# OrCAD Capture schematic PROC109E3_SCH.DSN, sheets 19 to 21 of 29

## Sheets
19 19. BOOSTERPACK_CONNECTOR: size C; title: BOOSTERPACK CONNECTOR
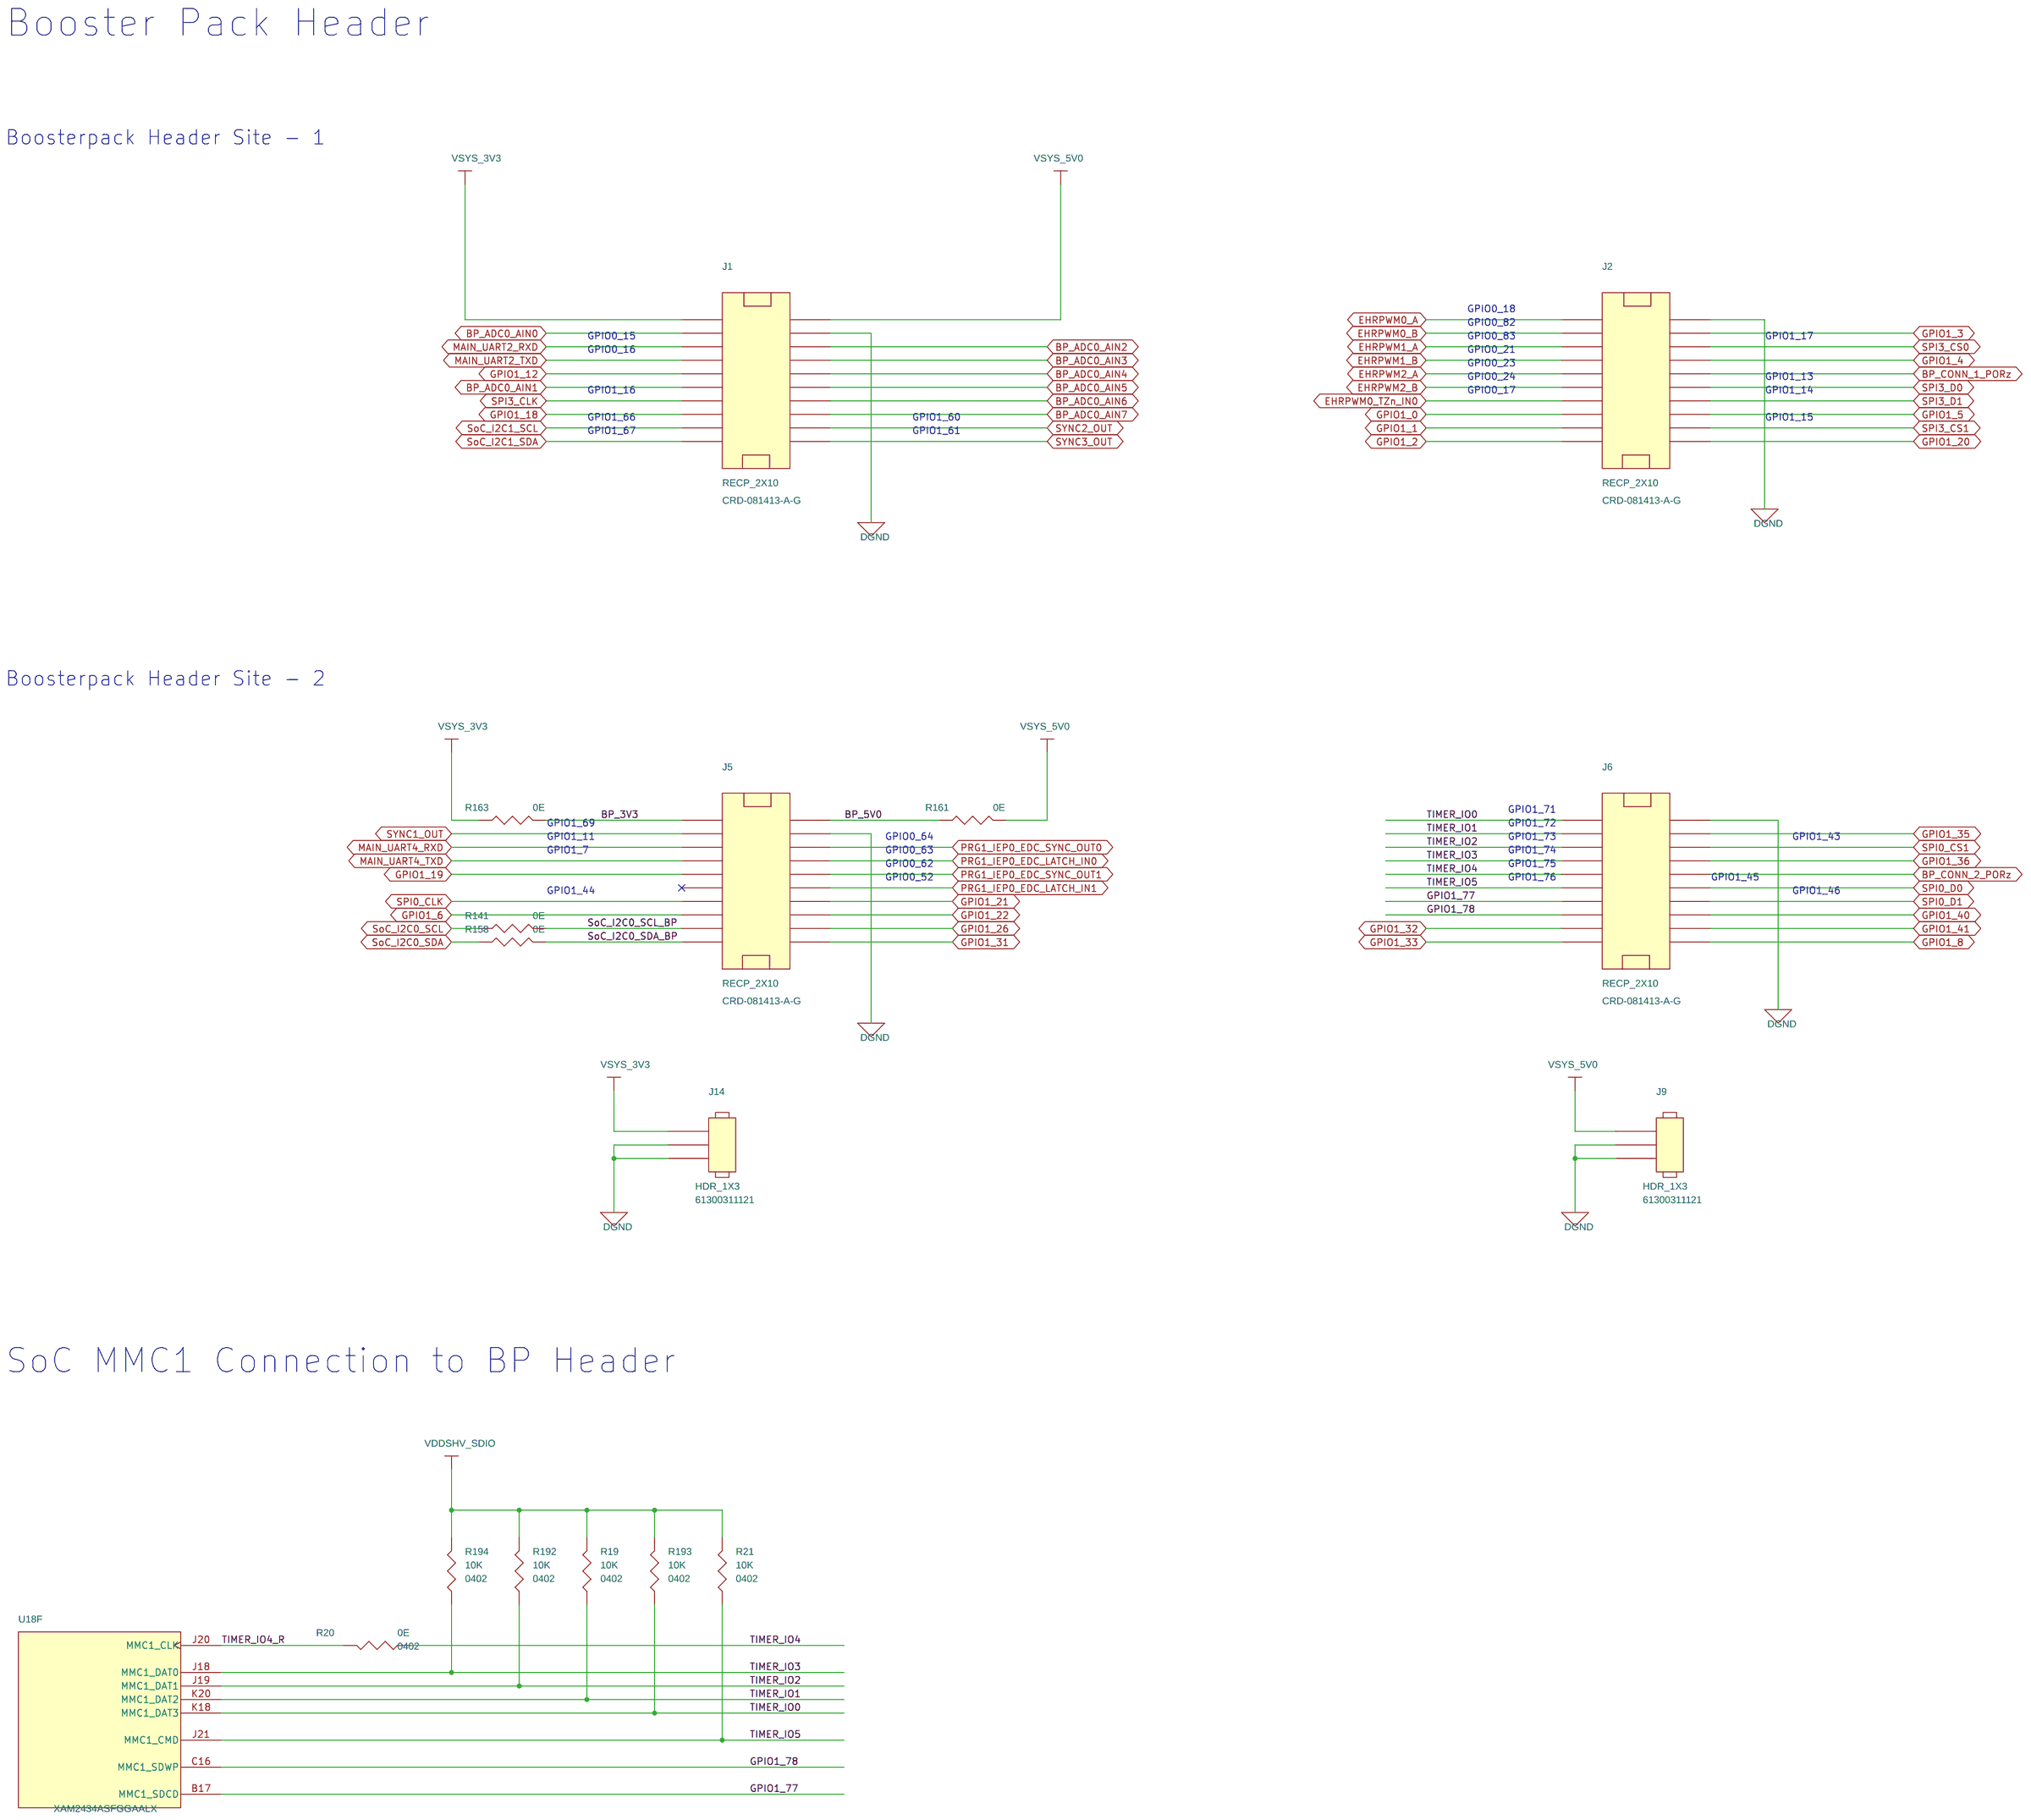
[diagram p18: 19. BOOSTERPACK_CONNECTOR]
20 20. TEST AUTOMATION HDR: size C; title: TEST AUTOMATION HEADER
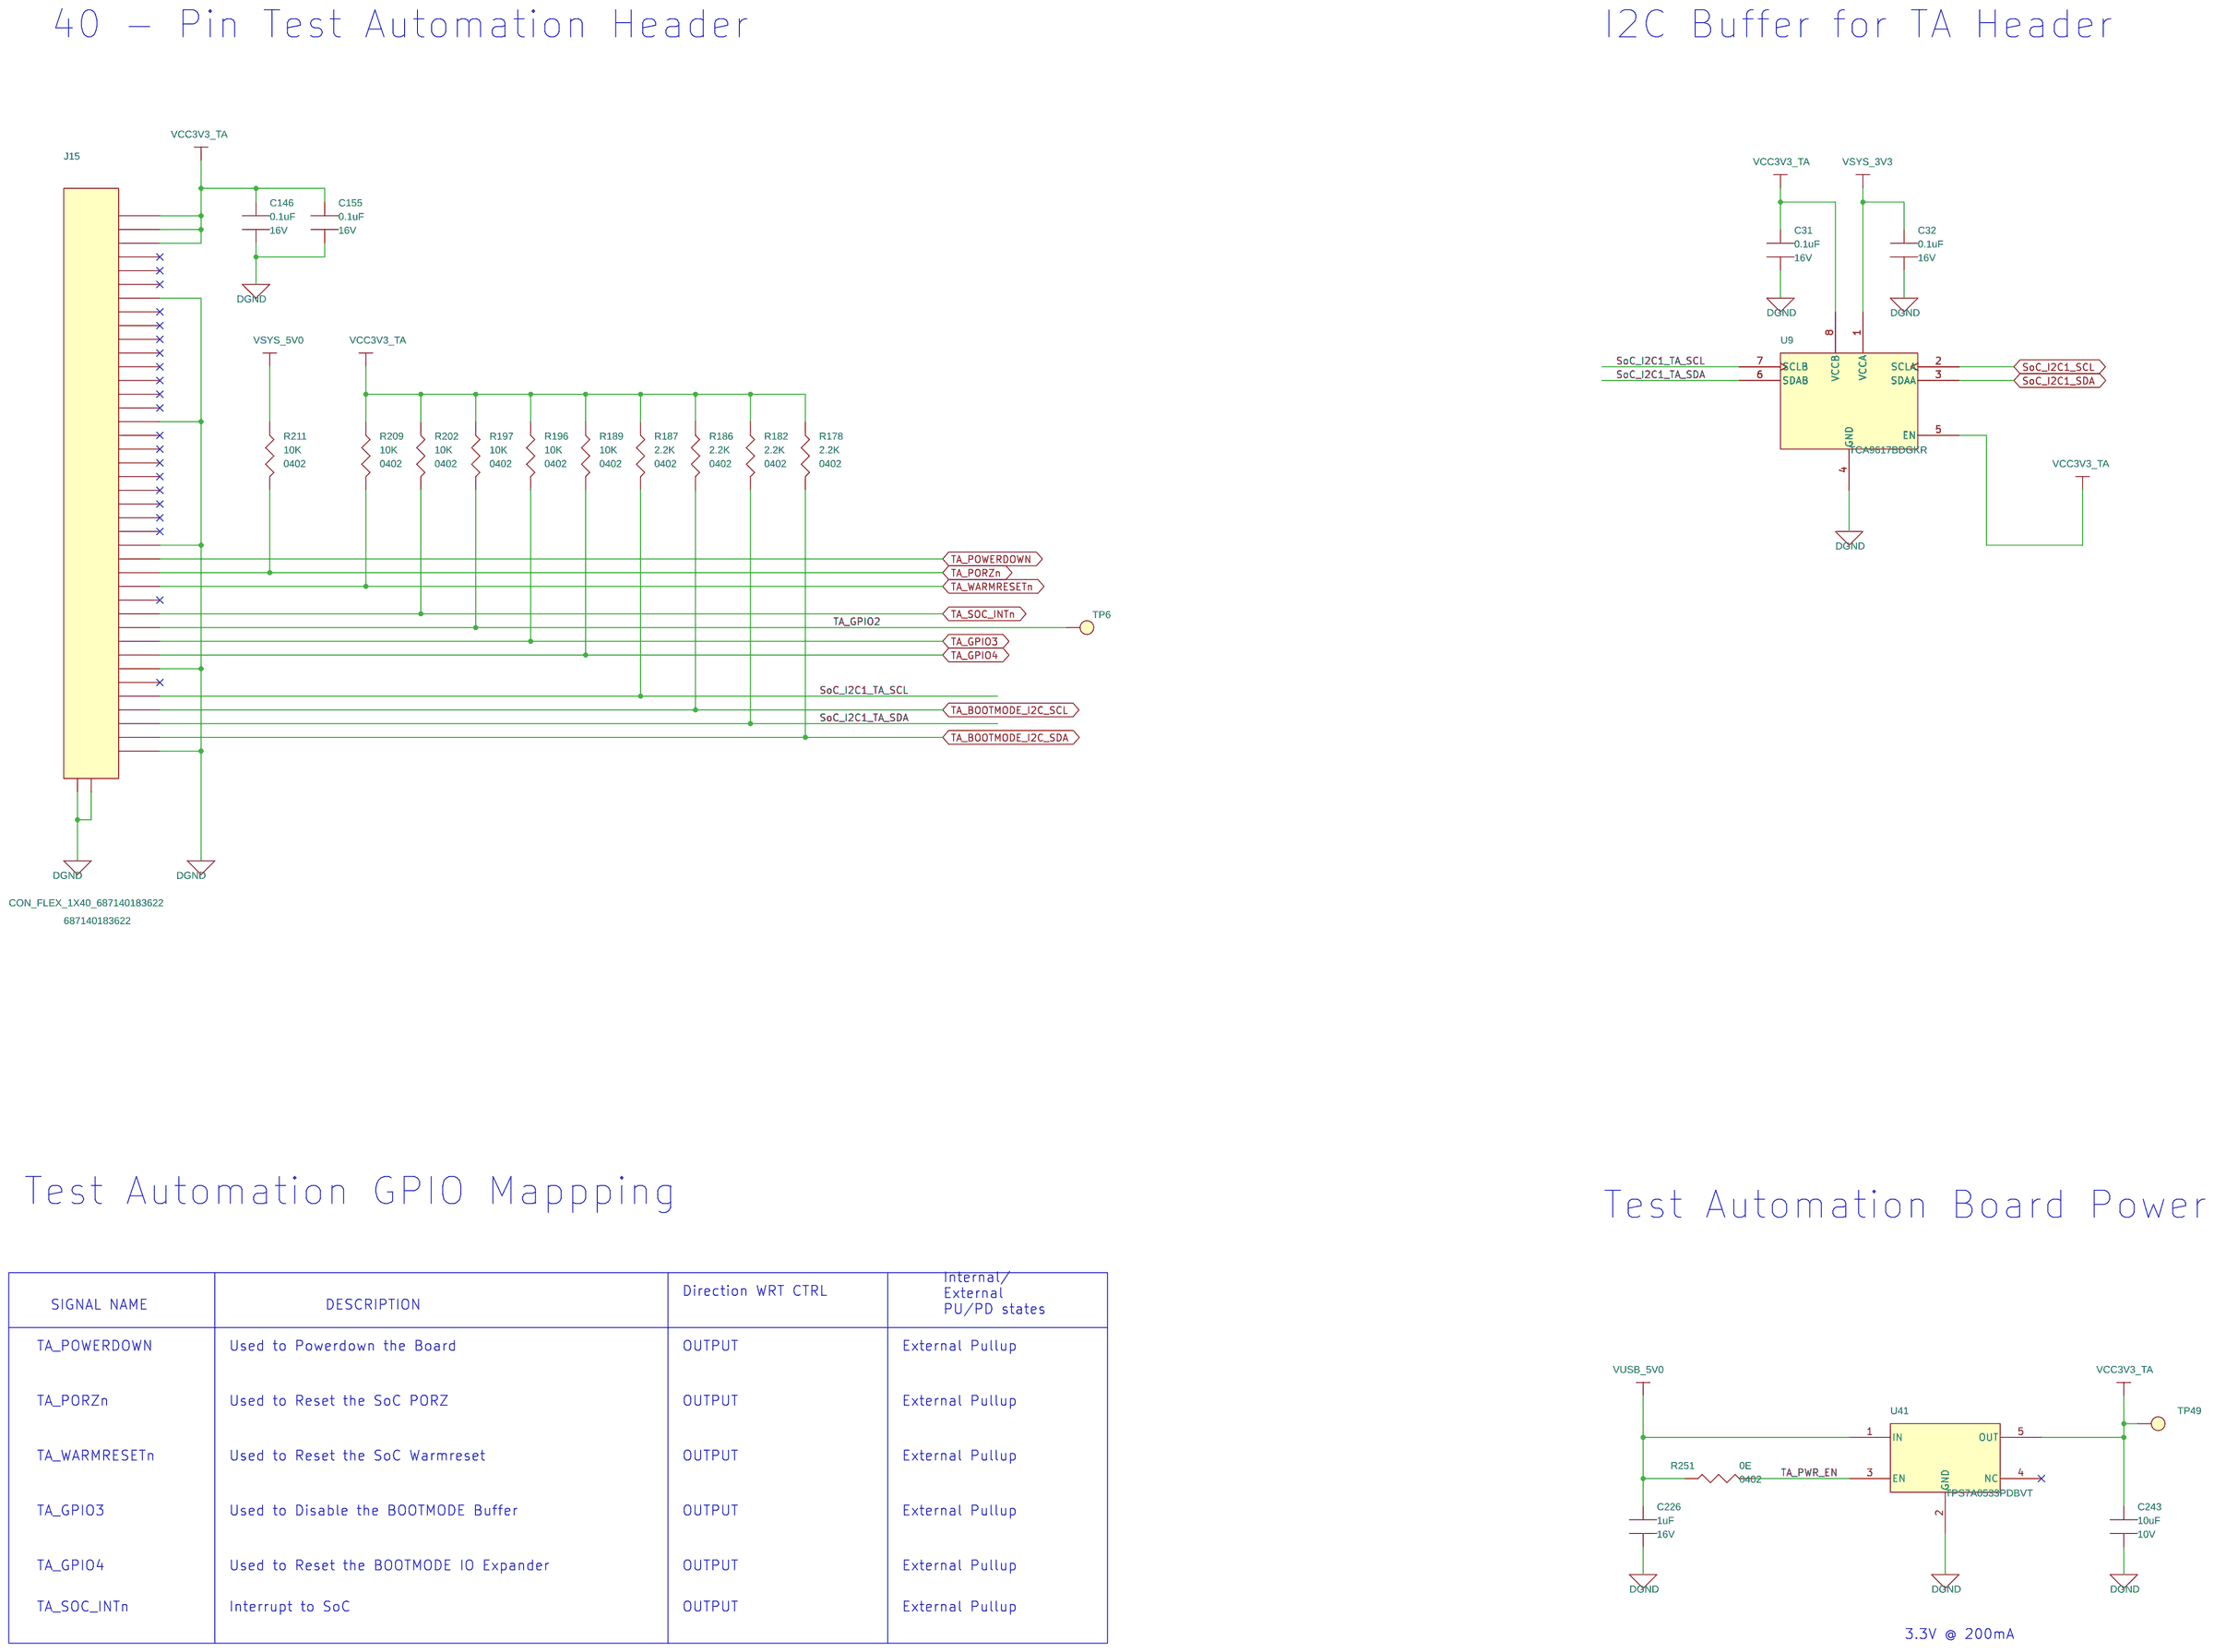
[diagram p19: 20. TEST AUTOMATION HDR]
21 21. BOOT MODE BUFFER & SWITCHES: size C; title: BOOT MODE BUFFER & SWITCHES
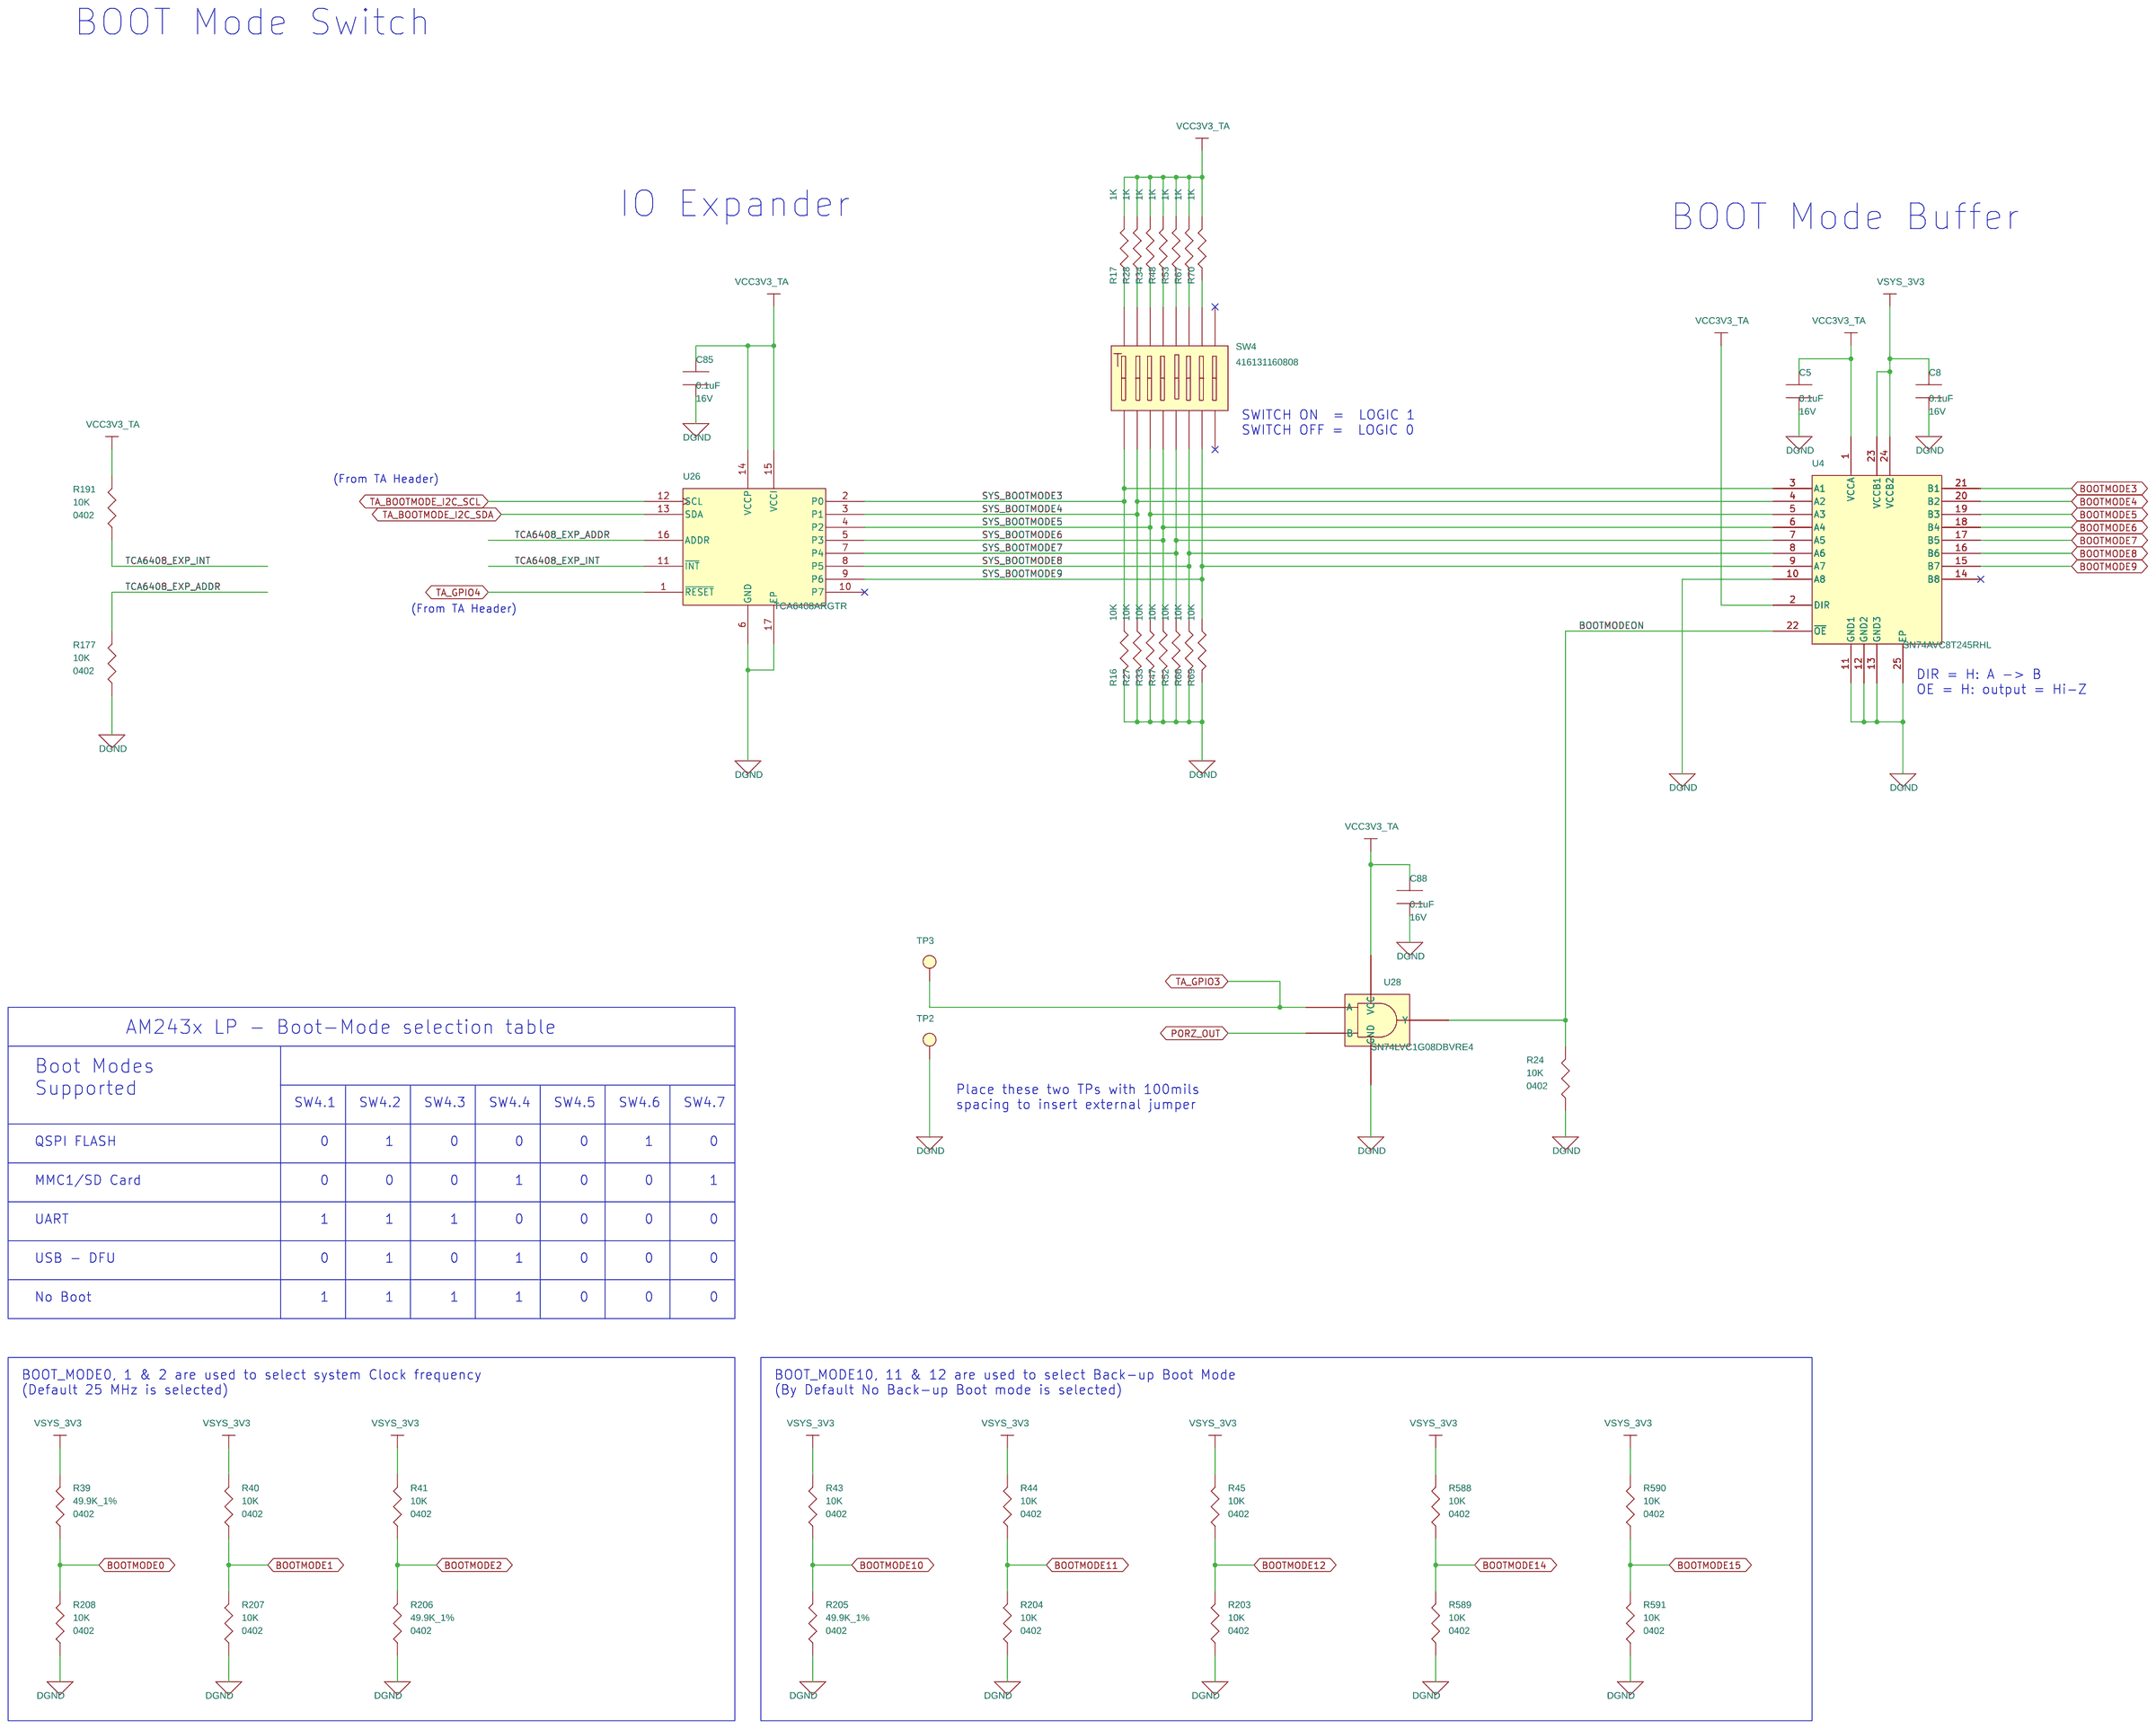
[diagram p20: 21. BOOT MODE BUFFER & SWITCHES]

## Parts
sheet 19. BOOSTERPACK_CONNECTOR
J1  RECP_2X10  [RECPT_2X10_CRD-081413-A_S_T_8-6]
J2  RECP_2X10  [RECPT_2X10_CRD-081413-A_S_T_8-6]
J5  RECP_2X10  [RECPT_2X10_CRD-081413-A_S_T_8-6]
J6  RECP_2X10  [RECPT_2X10_CRD-081413-A_S_T_8-6]
J9  HDR_1X3  [HDR_1X3_100_S_T]
J14  HDR_1X3  [HDR_1X3_100_S_T]
R19  10K  [RES0402_0-5]
R20  0E  [RES0402_0-5]
R21  10K  [RES0402_0-5]
R141  0E  [RES0402_0-5]
R158  0E  [RES0402_0-5]
R161  0E  [RES0402_0-5]
R163  0E  [RES0402_0-5]
R192  10K  [RES0402_0-5]
R193  10K  [RES0402_0-5]
R194  10K  [RES0402_0-5]
sheet 20. TEST AUTOMATION HDR
C31  0.1uF  [CAP0201_0-5]
C32  0.1uF  [CAP0201_0-5]
C146  0.1uF  [CAP0201_0-5]
C155  0.1uF  [CAP0201_0-5]
C226  1uF  [CAP0201_0-5]
C243  10uF  [CAP0402_0-75]
J15  CON_FLEX_1X40_687140183622  [CON_FLEX1X40_687140183622_S_R_S_1-3]
R178  2.2K  [RES0402_0-5]
R182  2.2K  [RES0402_0-5]
R186  2.2K  [RES0402_0-5]
R187  2.2K  [RES0402_0-5]
R189  10K  [RES0402_0-5]
R196  10K  [RES0402_0-5]
R197  10K  [RES0402_0-5]
R202  10K  [RES0402_0-5]
R209  10K  [RES0402_0-5]
R211  10K  [RES0402_0-5]
R251  0E  [RES0402_0-5]
TP6  TP20_SMD  [TP20_SMD]
TP49  TP20_SMD  [TP20_SMD]
U9  TCA9617BDGKR  [VSSOP8_25-59_120X120_1-1]
U41  TPS7A0533PDBVT  [SOT23-5_1-5]
sheet 21. BOOT MODE BUFFER & SWITCHES
C5  0.1uF  [CAP0201_0-5]
C8  0.1uF  [CAP0201_0-5]
C85  0.1uF  [CAP0201_0-5]
C88  0.1uF  [CAP0201_0-5]
R16  10K  [RES0402_0-5]
R17  1K  [RES0402_0-5]
R24  10K  [RES0402_0-5]
R27  10K  [RES0402_0-5]
R28  1K  [RES0402_0-5]
R33  10K  [RES0402_0-5]
R34  1K  [RES0402_0-5]
R39  49.9K_1%  [RES0402_0-5]
R40  10K  [RES0402_0-5]
R41  10K  [RES0402_0-5]
R43  10K  [RES0402_0-5]
R44  10K  [RES0402_0-5]
R45  10K  [RES0402_0-5]
R47  10K  [RES0402_0-5]
R48  1K  [RES0402_0-5]
R52  10K  [RES0402_0-5]
R53  1K  [RES0402_0-5]
R66  10K  [RES0402_0-5]
R67  1K  [RES0402_0-5]
R69  10K  [RES0402_0-5]
R70  1K  [RES0402_0-5]
R177  10K  [RES0402_0-5]
R191  10K  [RES0402_0-5]
R203  10K  [RES0402_0-5]
R204  10K  [RES0402_0-5]
R205  49.9K_1%  [RES0402_0-5]
R206  49.9K_1%  [RES0402_0-5]
R207  10K  [RES0402_0-5]
R208  10K  [RES0402_0-5]
R588  10K  [RES0402_0-5]
R589  10K  [RES0402_0-5]
R590  10K  [RES0402_0-5]
R591  10K  [RES0402_0-5]
SW4  416131160808  [SW16_416131160808_460X230_SMD_2-7]
TP2  THRU HOLE  [TP_40X65]
TP3  THRU HOLE  [TP_40X65]
U4  SN74AVC8T245RHL  [QFN24_19-68_220X140_1]
U26  TCA6408ARGTR  [QFN16_19-68_120X120_1_EP1-6]
U28  SN74LVC1G08DBVRE4  [SOT23-5]
sheet 25. SOC_ANALOG_POWER_DECAPs
U18  XAM2434ASFGGAALX  [BGA293_19-68_440X440_1]  (sections A,B,C,D,E,F,G,H,I,J,K,L,M)

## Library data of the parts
J1 J2 J5 J6 = RECP_10X2: CON RECP 2X10 2.54MM PITCH ST TH; Chkd/date: MANIRAJA/231120; Crtd /date: ALVY/201120; Custom_Duty: 24%; Customs_HS_Code: 85369090; Distributor_name: NA; Distributor_part_number: NA; Footprint Path: Y:\MIS_DATABASE\Library\ALTIUM_TOOL\PCB_FOOTPRINTS\Altium_Footprint_Lib.PcbLib; Height: 8.51MM; Library Path: Y:\MIS_DATABASE\Library\ALTIUM_TOOL\SCHEMATICS_PARTS\MS_CONNECTOR_Library.schlib; Mfr_name: MAJOR LEAGUE; Mfr_part_number: CRD-081413-A-G; Mistral Part No: 150020110025-R; Package: THRU-HOLE; Part_type: CONNECTOR\RECEPTACLE; Project: TI_AM243x LP EVM; RoHS: RoHS; Temperature: -40°C+105°C; Tolerance: NA; Voltage: NA; Wattage: NA; Weight: NA; Datasheet: Y:\MIS_DATABASE\DATASHEETS\CONNECTORS\CRD-081413-A.PDF
J9 J14 = HEADER_3X1: CON HDR 1X3 2.54MM PITCH ST TH; Chkd/date: VASANTHA/211015; Crtd /date: VASANTHA/211015; Custom_Duty: 24%; Customs_HS_Code: 85369090; Distributor_name: DIGIKEY; Distributor_part_number: 732-5316-ND; Height: 8.54MM; Mfr_name: WURTH ELECTRONICS INC; Mfr_part_number: 61300311121; Mistral Part No: 150015100037-R; Package: THRU-HOLE; Part_type: CONNECTOR\HEADERS; Project: CYPHY_ROADKILL; RoHS: RoHS; Temperature: NA; Tolerance: NA; Voltage: NA; Wattage: NA; Weight: NA; Datasheet: Y:\MIS_DATABASE\DATASHEETS\CONNECTORS\6130XXX.PDF
R16 R19 R21 R24 R27 R33 R40 R41 R43-R45 R47 R52 R66 R69 R177 R189 R191-R194 R196 R197 R202-R204 R207-R209 R211 R588-R591 = RESISTOR: RES 10K 1/16W 5% 0402; Chkd/date: VASANTHA/061216; Crtd /date: MAZHAR/230805; Custom_Duty: 15%; Customs_HS_Code: 85332119; Distributor_name: DIGIKEY; Distributor_part_number: 311-10KJRCT-ND; Footprint Path: Y:\MIS_DATABASE\Library\ALTIUM_TOOL\PCB_FOOTPRINTS\Altium_Footprint_Lib.PcbLib; Height: 0.40MM; Library Path: Y:\MIS_DATABASE\Library\ALTIUM_TOOL\SCHEMATICS_PARTS\MS_DISCRETE_Library.schlib; Mfr_name: YAGEO AMERICA; Mfr_part_number: RC0402JR-0710KL; Mistral Part No: 110011060021-R; Package: 0402; Part_type: RESISTORS\FIXED; Project: HSE; RoHS: RoHS; Temperature: -55°C+155°C; Tolerance: 5%; Voltage: NA; Wattage: 1/16W; Weight: 0.65mg; Datasheet: Y:\MIS_DATABASE\DATASHEETS\RESISTORS\RCXXXXL-SER_MAR18.PDF
R20 = RESISTOR: RES 0E 1/16W 5% 0402; Chkd/date: VASANTHA/291216; Crtd /date: CHAITHANYA/300911; Custom_Duty: 15%; Customs_HS_Code: 85332119; Distributor_name: DIGIKEY; Distributor_part_number: 311-0.0JRCT-ND; Footprint Path: Y:\MIS_DATABASE\Library\ALTIUM_TOOL\PCB_FOOTPRINTS\Altium_Footprint_Lib.PcbLib; Height: 0.40MM; Library Path: Y:\MIS_DATABASE\Library\ALTIUM_TOOL\SCHEMATICS_PARTS\MS_DISCRETE_Library.schlib; Mfr_name: YAGEO AMERICA; Mfr_part_number: RC0402JR-070RL; Mistral Part No: 110011090036-R; Package: 0402; Part_type: RESISTORS\FIXED; Project: VP-4000-PROCESSOR; RoHS: RoHS; SIGNAL_MODEL: RESISTOR_RES0402_0-5_0E_0E; Temperature: -55°C+155°C; Tolerance: 5%; Voltage: NA; Wattage: 1/16W; Weight: 0.65mg; Datasheet: Y:\MIS_DATABASE\DATASHEETS\RESISTORS\RCXXXXL-SER_MAR18.PDF
R141 R158 R161 R163 R251 = RESISTOR: RES 0E 1/16W 5% 0402; Chkd/date: VASANTHA/291216; Crtd /date: CHAITHANYA/300911; Custom_Duty: 15%; Customs_HS_Code: 85332119; Distributor_name: DIGIKEY; Distributor_part_number: 311-0.0JRCT-ND; Footprint Path: Y:\MIS_DATABASE\Library\ALTIUM_TOOL\PCB_FOOTPRINTS\Altium_Footprint_Lib.PcbLib; Height: 0.40MM; Library Path: Y:\MIS_DATABASE\Library\ALTIUM_TOOL\SCHEMATICS_PARTS\MS_DISCRETE_Library.schlib; Mfr_name: YAGEO AMERICA; Mfr_part_number: RC0402JR-070RL; Mistral Part No: 110011090036-R; Package: 0402; Part_type: RESISTORS\FIXED; Project: VP-4000-PROCESSOR; RoHS: RoHS; Temperature: -55°C+155°C; Tolerance: 5%; Voltage: NA; Wattage: 1/16W; Weight: 0.65mg; Datasheet: Y:\MIS_DATABASE\DATASHEETS\RESISTORS\RCXXXXL-SER_MAR18.PDF
C5 C8 C31 C32 C85 C88 C146 C155 = CAP: CAP CERAMIC 0.1uF 16V 10% X5R 0201; Alt_Mfr_name: YAGEO AMERICA; Alt_Mfr_part_number: CC0402KRX5R8BB104; Chkd/date: MANIRAJA/230118; Crtd /date: MANIRAJA/230118; Custom_Duty: 15%; Customs_HS_Code: 85322990; Distributor_name: DIGIKEY; Distributor_part_number: 490-14305-1-ND; Footprint Path: Y:\MIS_DATABASE\Library\ALTIUM_TOOL\PCB_FOOTPRINTS\Altium_Footprint_Lib.PcbLib; Height: 0.33MM; Library Path: Y:\MIS_DATABASE\Library\ALTIUM_TOOL\SCHEMATICS_PARTS\MS_DISCRETE_Library.schlib; Mfr_name: MURATA; Mfr_part_number: GRM033R61C104KE14D; Mistral Part No: 120009030072-R; Package: 0201; Part_type: CAPACITORS\CERAMIC; Project: TI_MAXIE_CPB; RoHS: RoHS; Temperature: -55°C+85°C; Tolerance: 10%; Voltage: 16V; Wattage: NA; Weight: 0.33mg; Datasheet: Y:\MIS_DATABASE\DATASHEETS\CAPACITORS\GRM033R61C104KE14.PDF
C226 = CAP: CAP CERAMIC 1uF 16V 20% X5R 0201; Chkd/date: MANIRAJA/300520; Crtd /date: ALVY/260520; Custom_Duty: 15%; Customs_HS_Code: 85322990; Distributor_name: DIGIKEY; Distributor_part_number: 490-18654-1-ND; Footprint Path: Y:\MIS_DATABASE\Library\ALTIUM_TOOL\PCB_FOOTPRINTS\Altium_Footprint_Lib.PcbLib; Height: 0.39MM; Library Path: Y:\MIS_DATABASE\Library\ALTIUM_TOOL\SCHEMATICS_PARTS\MS_DISCRETE_Library.schlib; Mfr_name: MURATA; Mfr_part_number: GRM033R61C105ME15D; Mistral Part No: 120018090038-R; Package: 0201; Part_type: CAPACITORS\CERAMIC; Project: QCS610_NANOSOM; RoHS: RoHS; Temperature: -55°C+85°C; Tolerance: 20%; Voltage: 16V; Wattage: NA; Weight: 0.33mg; Datasheet: Y:\MIS_DATABASE\DATASHEETS\CAPACITORS\GRM033R61C105ME15.PDF
C243 = CAP: CAP CERAMIC 10uF 10V 20% X5R 0402; Chkd/date: MANIRAJA/300520; Crtd /date: ALVY/260520; Custom_Duty: 15%; Customs_HS_Code: 85322990; Distributor_name: DIGIKEY; Distributor_part_number: 490-GRM155R61A106ME11DTR-ND; Footprint Path: Y:\MIS_DATABASE\Library\ALTIUM_TOOL\PCB_FOOTPRINTS\Altium_Footprint_Lib.PcbLib; Height: 0.55MM; Library Path: Y:\MIS_DATABASE\Library\ALTIUM_TOOL\SCHEMATICS_PARTS\MS_DISCRETE_Library.schlib; Mfr_name: MURATA; Mfr_part_number: GRM155R61A106ME11D; Mistral Part No: 120013110019-R; Package: 0402; Part_type: CAPACITORS\CERAMIC; Project: QCS610_NANOSOM; RoHS: RoHS; Temperature: -55°C+85°C; Tolerance: 20%; Voltage: 10V; Wattage: NA; Weight: 3.1mg; Datasheet: Y:\MIS_DATABASE\DATASHEETS\CAPACITORS\MURATA-GXX-SER_NOV17.PDF
J15 = CON_FLEX_40X1_20347: CON FPC 1X40 0.50MM PITCH FEMALE RT SMD; Chkd/date: ALVY/101220; Crtd /date: MANIRAJA/101220; Custom_Duty: 24%; Customs_HS_Code: 85369090; Distributor_name: NA; Distributor_part_number: NA; Footprint Path: Y:\MIS_DATABASE\Library\ALTIUM_TOOL\PCB_FOOTPRINTS\Altium_Footprint_Lib.PcbLib; Height: 1.30MM; Library Path: Y:\MIS_DATABASE\Library\ALTIUM_TOOL\SCHEMATICS_PARTS\MS_CONNECTOR_Library.schlib; Mfr_name: WURTH ELEKTRONIK; Mfr_part_number: 687140183622; Mistral Part No: 150020120010-R; Package: SMD; Part_type: CONNECTOR\FPC; Project: TI_AM243x LP EVM; RoHS: RoHS; Temperature: -25°C+85°C; Tolerance: NA; Voltage: NA; Wattage: NA; Weight: NA; Datasheet: Y:\MIS_DATABASE\DATASHEETS\CONNECTORS\687140183622.PDF
R178 R182 R186 R187 = RESISTOR: RES 2.2K 1/16W 5% 0402; Chkd/date: VASANTHA/061216; Crtd /date: BAVISH/021210; Custom_Duty: 15%; Customs_HS_Code: 85332119; Distributor_name: DIGIKEY; Distributor_part_number: 311-2.2KJRCT-ND; Footprint Path: Y:\MIS_DATABASE\Library\ALTIUM_TOOL\PCB_FOOTPRINTS\Altium_Footprint_Lib.PcbLib; Height: 0.40MM; Library Path: Y:\MIS_DATABASE\Library\ALTIUM_TOOL\SCHEMATICS_PARTS\MS_DISCRETE_Library.schlib; Mfr_name: YAGEO AMERICA; Mfr_part_number: RC0402JR-072K2L; Mistral Part No: 110010120018-R; Package: 0402; Part_type: RESISTORS\FIXED; Project: TE4; RoHS: RoHS; Temperature: -55°C+155°C; Tolerance: 5%; Voltage: NA; Wattage: 1/16W; Weight: 0.65mg; Datasheet: Y:\MIS_DATABASE\DATASHEETS\RESISTORS\RCXXXXL-SER_MAR18.PDF
TP6 TP49 = TESTPOINT: TESTPOINT CIR 20 SMD; Chkd/date: SHREESHAIL/171006; Crtd /date: MAZHAR/171006; Custom_Duty: NA; Customs_HS_Code: NA; Distributor_name: NA; Distributor_part_number: NA; Footprint Path: Y:\MIS_DATABASE\Library\ALTIUM_TOOL\PCB_FOOTPRINTS\Altium_Footprint_Lib.PcbLib; Height: NA; Library Path: Y:\MIS_DATABASE\Library\ALTIUM_TOOL\SCHEMATICS_PARTS\MS_DISCRETE_Library.schlib; MECHANICAL 3D STEP FILE: NA; Mfr_name: LOCAL; Mistral Part No: NA; Package: SMD; Project: BT MODULE_CSRBC04; RoHS: NA; Temperature: NA; Tolerance: NA; Voltage: NA; Wattage: NA; Weight: NA; Datasheet: NA
U9 = TCA9617BDGKR_VSSOP8: IC FM+I2C BUS REPEATER LEVEL TRANSLATOR VSSOP8; Chkd/date: MANIRAJA/131017; Crtd /date: MANIRAJA/131017; Custom_Duty: 15%; Customs_HS_Code: 85423100; Distributor_name: DIGIKEY; Distributor_part_number: 296-40579-1-ND; Height: 1.10MM; Mfr_name: TEXAS INSTRUMENTS; Mistral Part No: 141017100010-R; Package: VSSOP8; Part_type: ICS\INTERFACE\LEVEL TRANSLATOR; Project: TI_MAXIE_CPB; RoHS: RoHS; Temperature: -40°C+85°C; Tolerance: NA; Voltage: NA; Wattage: NA; Weight: NA; Datasheet: Y:\MIS_DATABASE\DATASHEETS\ICS\INTERFACE\TCA9617B.PDF
U41 = TLV71318PDBVT_SOT23-5: IC 1uA ULTRA-LOW IQ 200mA LDO REGULATOR SOT23-5; Chkd/date: MANIRAJA/131120; Crtd /date: ALVY/121120; Custom_Duty: 15%; Customs_HS_Code: 85423100; Distributor_name: DIGIKEY; Distributor_part_number: 296-50256-1-ND; Footprint Path: Y:\MIS_DATABASE\Library\ALTIUM_TOOL\PCB_FOOTPRINTS\Altium_Footprint_Lib.PcbLib; Height: 1.45MM; Library Path: Y:\MIS_DATABASE\Library\ALTIUM_TOOL\SCHEMATICS_PARTS\MS_MISCPOWER_Library.schlib; Mfr_name: TEXAS INSTRUMENTS; Mistral Part No: 142020110015-R; Package: SOT23-5; Part_type: ICS\POWER\VOLTAGE REGULATOR; Project: TI_AM243x LP EVM; RoHS: RoHS; Temperature: -40°C+125°C; Tolerance: NA; Voltage: NA; Wattage: NA; Weight: 25.3mg; Datasheet: Y:\MIS_DATABASE\DATASHEETS\MISC\REGULATORS\TPS7A05XX.PDF
R17 R28 R34 R48 R53 R67 R70 = RESISTOR: RES 1K 1/16W 5% 0402; Chkd/date: VASANTHA/120516; Crtd /date: VASANTHA/120516; Custom_Duty: 15%; Customs_HS_Code: 85332119; Distributor_name: DIGIKEY; Distributor_part_number: 311-1.0KJRCT-ND; Footprint Path: Y:\MIS_DATABASE\Library\ALTIUM_TOOL\PCB_FOOTPRINTS\Altium_Footprint_Lib.PcbLib; Height: 0.40MM; Library Path: Y:\MIS_DATABASE\Library\ALTIUM_TOOL\SCHEMATICS_PARTS\MS_DISCRETE_Library.schlib; Mfr_name: YAGEO AMERICA; Mfr_part_number: RC0402JR-071KL; Mistral Part No: 110010070006-R; Package: 0402; Part_type: RESISTORS\FIXED; Project: TMDXCSK368; RoHS: RoHS; Temperature: -55°C+155°C; Tolerance: 5%; Voltage: NA; Wattage: 1/16W; Weight: 0.65mg; Datasheet: Y:\MIS_DATABASE\DATASHEETS\RESISTORS\RCXXXXL-SER_MAR18.PDF
R39 R205 R206 = RESISTOR: RES 49.9K 1/10W 1% 0402; Chkd/date: MANIRAJA/130617; Crtd /date: BAVISH/020611; Custom_Duty: 15%; Customs_HS_Code: 85332119; Distributor_name: DIGIKEY; Distributor_part_number: P49.9KLCT-ND; Footprint Path: Y:\MIS_DATABASE\Library\ALTIUM_TOOL\PCB_FOOTPRINTS\Altium_Footprint_Lib.PcbLib; Height: 0.40MM; Library Path: Y:\MIS_DATABASE\Library\ALTIUM_TOOL\SCHEMATICS_PARTS\MS_DISCRETE_Library.schlib; Mfr_name: PANASONIC-ECG; Mfr_part_number: ERJ-2RKF4992X; Mistral Part No: 110011060018-R; Package: 0402; Part_type: RESISTORS\FIXED; Project: AM4515_EVM_LCD; RoHS: RoHS; Temperature: -55°C+155°C; Tolerance: 1%; Voltage: NA; Wattage: 1/10W; Weight: 0.8mg; Datasheet: Y:\MIS_DATABASE\DATASHEETS\RESISTORS\PAN-ERJSER_NOV17.PDF
SW4 = SW16_CHS-08A: SWITCH SLIDE SPST ST SMD; Chkd/date: MANIRAJA/051020; Crtd /date: ALVY/011020; Custom_Duty: 24%; Customs_HS_Code: 85369090; Distributor_name: DIGIKEY; Distributor_part_number: 732-3857-1-ND; Footprint Path: Y:\MIS_DATABASE\Library\ALTIUM_TOOL\PCB_FOOTPRINTS\Altium_Footprint_Lib.PcbLib; Height: 2.65MM; Library Path: Y:\MIS_DATABASE\Library\ALTIUM_TOOL\SCHEMATICS_PARTS\MS_SWITCH_Library.schlib; Mfr_name: WURTH ELECTRONICS; Mistral Part No: 130020100001-R; Package: SMD; Part_type: ELECTRO-MECHANICAL\SWITCH; Project: AM64X_SKEVM; RoHS: RoHS; Temperature: -40°C+85°C; Tolerance: NA; Voltage: NA; Wattage: NA; Weight: 281.7mg; Datasheet: Y:\MIS_DATABASE\DATASHEETS\MISC\SWITCHES\4161311608XX.PDF
TP2 TP3 = TESTPOINT: TESTPOINT 1.0MM DRILL PTH; Chkd/date: MAZHAR/271211; Crtd /date: SHREESHAIL/041005; Distributor_name: NA; Distributor_part_number: NA; Height: NA; Mfr_name: LOCAL; Mistral Part No: 130009030938; Package: THRU-HOLE; Project: HSE; Datasheet: NA
U4 = SN74AVC8T245RHL_QFN24: IC BUS TRANSCEIVER 8-BIT DUAL-SUPPLY QFN24; Chkd/date: VASANTHA/231216; Crtd /date: BAVISH/290411; Custom_Duty: 15%; Customs_HS_Code: 85423100; Distributor_name: DIGIKEY; Distributor_part_number: 296-17859-1-ND; Height: 1.00MM; Mfr_name: TEXAS INSTRUMENTS; Mfr_part_number: SN74AVC8T245RHLR; Mistral Part No: 143011040001-R; Package: QFN24; Part_type: ICS\TELECOM\TRANSCEIVER; Project: OMAPL1_PEC20; RoHS: RoHS; Temperature: -40°C+85°C; Tolerance: NA; Voltage: NA; Wattage: NA; Weight: NA; Datasheet: Y:\MIS_DATABASE\DATASHEETS\ICS\DIGITAL\BUSTRANSCEIVER\SN74AVC8T245.PDF
U26 = TCA6408ARGTR_VQFN16: IC 8-BIT I2C AND SMBUS I/O EXPANDER WITH INTERRUPT O/P VQFN16; Chkd/date: MANIRAJA/151018; Crtd /date: MANIRAJA/151018; Custom_Duty: 15%; Customs_HS_Code: 85423100; Distributor_name: DIGIKEY; Distributor_part_number: 296-24825-1-ND; Footprint Path: Y:\MIS_DATABASE\Library\ALTIUM_TOOL\PCB_FOOTPRINTS\Altium_Footprint_Lib.PcbLib; Height: 1.00MM; Library Path: Y:\MIS_DATABASE\Library\ALTIUM_TOOL\SCHEMATICS_PARTS\MS_MISCINTERFACE_Library.schlib; Mfr_name: TEXAS INSTRUMENTS; Mistral Part No: 141018100011-R; Package: VQFN16; Part_type: ICS\INTERFACE; Project: TI_60GHz-AOP; RoHS: RoHS; Temperature: -40°C+85°C; Tolerance: NA; Voltage: NA; Wattage: NA; Weight: 24.1mg; Datasheet: Y:\MIS_DATABASE\DATASHEETS\ICS\INTERFACE\TCA6408AXX.PDF
U28 = SN74LVC1G08DBVRE4_SOT23-5: IC SINGLE 2-INPUT POSITIVE AND GATE SOT23-5; Automotive Alternate_mfr_name: TEXAS INSTRUMENTS; Automotive Alternate_mfr_part_number: SN74LVC1G08QDBVRQ1; Chkd/date: SUHAS/221010; Crtd /date: USMAN/151008; Custom_Duty: 15%; Customs_HS_Code: 85423100; Distributor_name: DIGIKEY; Distributor_part_number: SN74LVC1G08DBVRE4-ND; Height: 1.45MM; Mfr_name: TEXAS INSTRUMENTS; Mistral Part No: 141009060026-R; Part_type: ICS\DIGITAL\GATES; Project: KHAN_MAIN; RoHS: Sb/ Br FREE; Temperature: -40°C+85°C; Datasheet: Y:\MIS_DATABASE\DATASHEETS\ICS\DIGITAL\GATES\SN74LVC1G08.PDF
U18 = AM243X_SOC_LP_EVM_BGA293: IC AM243x SoC_LP_EVM MICROPROCESSOR BGA293; Chkd/date: MANIRAJA/131120; Crtd /date: ALVY/121120; Custom_Duty: 15%; Customs_HS_Code: 85423100; Distributor_name: NA; Distributor_part_number: NA; Footprint Path: Y:\MIS_DATABASE\Library\ALTIUM_TOOL\PCB_FOOTPRINTS\Altium_Footprint_Lib.PcbLib; Height: 1.00MM; Library Path: Y:\MIS_DATABASE\Library\ALTIUM_TOOL\SCHEMATICS_PARTS\MS_MICROPROCESSOR_Library.schlib; Library Ref: AM243x SoC_LP_EVM_BGA293; Mfr_name: TEXAS INSTRUMENTS; Mistral Part No: 141220110003; Package: BGA293; Part_type: ICS\DIGITAL\MICROPROCESSOR; Project: TI_AM243x LP EVM; RoHS: NA; Temperature: NA; Tolerance: NA; Voltage: NA; Wattage: NA; Weight: NA; Datasheet: Y:\MIS_DATABASE\DATASHEETS\ICS\DIGITAL\MICROCONTROLLER\AM243x SoC-FP.PDF

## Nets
DGND: C5.2 C8.2 C31.2 C32.2 C85.2 C88.2 C146.2 C155.2 C226.2 C243.2 J1.4 J2.2 J5.4 J6.2 J9.2 J9.3 J14.2 J14.3 J15.7 J15.16 J15.25 J15.34 J15.40 J15.41 J15.42 R16.2 R24.1 R27.2 R33.2 R47.2 R52.2 R66.2 R69.2 R177.1 R203.1 R204.1 R205.1 R206.1 R207.1 R208.1 R589.1 R591.1 TP2.1(TP) U4.10(A8) U4.11(GND1) U4.12(GND2) U4.13(GND3) U4.25(EP) U9.4(GND) U26.6(GND) U26.17(EP) U28.3(GND) U41.2(GND) ; also on sheet 10 11 12 13 14 15 16 17 18 22 23 24 25 26 27 28
VCC3V3_TA: C5.1 C31.1 C85.1 C88.1 C146.1 C155.1 C243.1 J15.1 J15.2 J15.3 R17.2 R28.2 R34.2 R48.2 R53.2 R67.2 R70.2 R178.1 R182.1 R186.1 R187.1 R189.2 R191.2 R196.2 R197.2 R202.2 R209.2 TP49.1(TP) U4.1(VCCA) U4.2(DIR) U9.5(EN) U9.8(VCCB) U26.14(VCCP) U26.15(VCCI) U28.5(VCC) U41.5(OUT)
VDDSHV_SDIO: R19.2 R21.2 R192.2 R193.2 R194.2 ; also on sheet 24
BOOTMODE0: R39.1 R208.2 ; also on sheet 11
BOOTMODE1: R40.1 R207.2 ; also on sheet 11
BOOTMODE2: R41.1 R206.2 ; also on sheet 11
BOOTMODE3: U4.21(B1) ; also on sheet 11
BOOTMODE4: U4.20(B2) ; also on sheet 11
BOOTMODE5: U4.19(B3) ; also on sheet 11
BOOTMODE6: U4.18(B4) ; also on sheet 11
BOOTMODE7: U4.17(B5) ; also on sheet 11
BOOTMODE8: U4.16(B6) ; also on sheet 11
BOOTMODE9: U4.15(B7) ; also on sheet 11
BOOTMODE10: R43.1 R205.2 ; also on sheet 11
BOOTMODE11: R44.1 R204.2 ; also on sheet 11
BOOTMODE12: R45.1 R203.2 ; also on sheet 11
BOOTMODE14: R588.1 R589.2 ; also on sheet 11
BOOTMODE15: R590.1 R591.2 ; also on sheet 11
BOOTMODEON: R24.2 U4.22(~{OE}) U28.4(Y)
BP_3V3: J5.1 R163.2
BP_5V0: J5.2 R161.1
BP_ADC0_AIN0: J1.3 ; also on sheet 16
BP_ADC0_AIN1: J1.11 ; also on sheet 16
BP_ADC0_AIN2: J1.6 ; also on sheet 16
BP_ADC0_AIN3: J1.8 ; also on sheet 16
BP_ADC0_AIN4: J1.10 ; also on sheet 16
BP_ADC0_AIN5: J1.12 ; also on sheet 16
BP_ADC0_AIN6: J1.14 ; also on sheet 16
BP_ADC0_AIN7: J1.16 ; also on sheet 16
BP_CONN_1_PORz: J2.10 ; also on sheet 10
BP_CONN_2_PORz: J6.10 ; also on sheet 10
EHRPWM0_A: J2.1 ; also on sheet 11
EHRPWM0_B: J2.3 ; also on sheet 11
EHRPWM0_TZn_IN0: J2.13 ; also on sheet 11
EHRPWM1_A: J2.5 ; also on sheet 11
EHRPWM1_B: J2.7 ; also on sheet 11
EHRPWM2_A: J2.9 ; also on sheet 13
EHRPWM2_B: J2.11 ; also on sheet 13
GPIO1_0: J2.15 ; also on sheet 11
GPIO1_1: J2.17 ; also on sheet 11
GPIO1_2: J2.19 ; also on sheet 11
GPIO1_3: J2.4 ; also on sheet 11
GPIO1_4: J2.8 ; also on sheet 11
GPIO1_5: J2.16 ; also on sheet 11
GPIO1_6: J5.15 ; also on sheet 11
GPIO1_8: J6.20 ; also on sheet 11
GPIO1_12: J1.9 ; also on sheet 11
GPIO1_18: J1.15 ; also on sheet 11
GPIO1_19: J5.9 ; also on sheet 11
GPIO1_20: J2.20 ; also on sheet 11
GPIO1_21: J5.14 ; also on sheet 11
GPIO1_22: J5.16 ; also on sheet 11
GPIO1_26: J5.18 ; also on sheet 11
GPIO1_31: J5.20 ; also on sheet 11
GPIO1_32: J6.17 ; also on sheet 11
GPIO1_33: J6.19 ; also on sheet 11
GPIO1_35: J6.4 ; also on sheet 11
GPIO1_36: J6.8 ; also on sheet 11
GPIO1_40: J6.16 ; also on sheet 11
GPIO1_41: J6.18 ; also on sheet 11
GPIO1_77: J6.13 U18.B17(MMC1_SDCD)
GPIO1_78: J6.15 U18.C16(MMC1_SDWP)
MAIN_UART2_RXD: J1.5 ; also on sheet 11
MAIN_UART2_TXD: J1.7 ; also on sheet 11
MAIN_UART4_RXD: J5.5 ; also on sheet 11
MAIN_UART4_TXD: J5.7 ; also on sheet 11
PORZ_OUT: U28.2(B) ; also on sheet 11 12 15 17 18
PRG1_IEP0_EDC_LATCH_IN0: J5.8 ; also on sheet 12
PRG1_IEP0_EDC_LATCH_IN1: J5.12 ; also on sheet 12
PRG1_IEP0_EDC_SYNC_OUT0: J5.6 ; also on sheet 12
PRG1_IEP0_EDC_SYNC_OUT1: J5.10 ; also on sheet 12
SoC_I2C0_SCL: R141.1 ; also on sheet 11 15 23
SoC_I2C0_SCL_BP: J5.17 R141.2
SoC_I2C0_SDA: R158.1 ; also on sheet 11 15 23
SoC_I2C0_SDA_BP: J5.19 R158.2
SoC_I2C1_SCL: J1.17 U9.2(SCLA) ; also on sheet 11
SoC_I2C1_SDA: J1.19 U9.3(SDAA) ; also on sheet 11
SoC_I2C1_TA_SCL: J15.36 R187.2 U9.7(SCLB)
SoC_I2C1_TA_SDA: J15.38 R182.2 U9.6(SDAB)
SPI0_CLK: J5.13 ; also on sheet 11
SPI0_CS1: J6.6 ; also on sheet 11
SPI0_D0: J6.12 ; also on sheet 11
SPI0_D1: J6.14 ; also on sheet 11
SPI3_CLK: J1.13 ; also on sheet 11
SPI3_CS0: J2.6 ; also on sheet 11
SPI3_CS1: J2.18 ; also on sheet 11
SPI3_D0: J2.12 ; also on sheet 11
SPI3_D1: J2.14 ; also on sheet 11
SYNC1_OUT: J5.3 ; also on sheet 11
SYNC2_OUT: J1.18 ; also on sheet 13
SYNC3_OUT: J1.20 ; also on sheet 13
SYS_BOOTMODE3: R16.1 SW4.1 U4.3(A1) U26.2(P0)
SYS_BOOTMODE4: R27.1 SW4.2 U4.4(A2) U26.3(P1)
SYS_BOOTMODE5: R33.1 SW4.3 U4.5(A3) U26.4(P2)
SYS_BOOTMODE6: R47.1 SW4.4 U4.6(A4) U26.5(P3)
SYS_BOOTMODE7: R52.1 SW4.5 U4.7(A5) U26.7(P4)
SYS_BOOTMODE8: R66.1 SW4.6 U4.8(A6) U26.8(P5)
SYS_BOOTMODE9: R69.1 SW4.7 U4.9(A7) U26.9(P6)
TA_BOOTMODE_I2C_SCL: J15.37 R186.2 U26.12(SCL)
TA_BOOTMODE_I2C_SDA: J15.39 R178.2 U26.13(SDA)
TA_GPIO2: J15.31 R197.1 TP6.1(TP)
TA_GPIO3: J15.32 R196.1 TP3.1(TP) U28.1(A)
TA_GPIO4: J15.33 R189.1 U26.1(~{RESET})
TA_PORZn: J15.27 R211.1 ; also on sheet 10
TA_POWERDOWN: J15.26 ; also on sheet 27
TA_PWR_EN: R251.2 U41.3(EN)
TA_SOC_INTn: J15.30 R202.1 ; also on sheet 10
TA_WARMRESETn: J15.28 R209.1 ; also on sheet 10
TCA6408_EXP_ADDR: R177.2 U26.16(ADDR)
TCA6408_EXP_INT: R191.1 U26.11(~{INT})
TIMER_IO0: J6.1 R193.1 U18.K18(MMC1_DAT3)
TIMER_IO1: J6.3 R19.1 U18.K20(MMC1_DAT2)
TIMER_IO2: J6.5 R192.1 U18.J19(MMC1_DAT1)
TIMER_IO3: J6.7 R194.1 U18.J18(MMC1_DAT0)
TIMER_IO4: J6.9 R20.1
TIMER_IO4_R: R20.2 U18.J20(MMC1_CLK)
TIMER_IO5: J6.11 R21.1 U18.J21(MMC1_CMD)
VSYS_3V3: C8.1 C32.1 J1.1 J14.1 R39.2 R40.2 R41.2 R43.2 R44.2 R45.2 R163.1 R588.2 R590.2 U4.23(VCCB1) U4.24(VCCB2) U9.1(VCCA) ; also on sheet 10 11 12 13 14 15 16 17 18 22 23 24 25 27 28
VSYS_5V0: J1.2 J9.1 R161.2 R211.2 ; also on sheet 10 13 14 25 26 27 28
VUSB_5V0: C226.1 R251.1 U41.1(IN) ; also on sheet 26
N29126233: R67.1 SW4.11
N29126235: R53.1 SW4.12
N29126237: R48.1 SW4.13
N29126239: R34.1 SW4.14
N29126243: R70.1 SW4.10
N29126245: R28.1 SW4.15
N29126269: R17.1 SW4.16

Not connected (* = marked no-connect by the designer): J5 11*; J15 4* 5* 6* 8* 9* 10* 11* 12* 13* 14* 15* 17* 18* 19* 20* 21* 22* 23* 24* 29* 35*; SW4 8* 9*; U4 14(B8)*; U26 10(P7)*; U41 4(NC)*

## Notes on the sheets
sheet 19
- Booster Pack Header
- Boosterpack Header Site - 1
- GPIO0_18
- GPIO0_15
- GPIO0_82
- GPIO0_83
- GPIO1_17
- GPIO0_16
- GPIO0_21
- GPIO0_23
- GPIO0_24
- GPIO1_13
- GPIO1_16
- GPIO0_17
- GPIO1_14
- GPIO1_66
- GPIO1_60
- GPIO1_15
- GPIO1_67
- GPIO1_61
- Boosterpack Header Site - 2
- GPIO1_71
- GPIO1_69
- GPIO1_72
- GPIO1_11
- GPIO0_64
- GPIO1_73
- GPIO1_43
- GPIO1_7
- GPIO0_62
- GPIO0_63
- GPIO1_74
- GPIO1_75
- GPIO0_52
- GPIO1_76
- GPIO1_45
- GPIO1_44
- GPIO1_46
- SoC MMC1 Connection to BP Header
sheet 20
- 40 - Pin Test Automation Header
- I2C Buffer for TA Header
- Test Automation GPIO Mappping
- Test Automation Board Power
- Direction WRT CTRL
- Internal/
  External
  PU/PD states
- SIGNAL NAME
- DESCRIPTION
- TA_POWERDOWN
- Used to Powerdown the Board
- OUTPUT
- External Pullup
- TA_PORZn
- Used to Reset the SoC PORZ
- OUTPUT
- External Pullup
- TA_WARMRESETn
- Used to Reset the SoC Warmreset
- OUTPUT
- External Pullup
- TA_GPIO3
- Used to Disable the BOOTMODE Buffer
- OUTPUT
- External Pullup
- TA_GPIO4
- Used to Reset the BOOTMODE IO Expander
- OUTPUT
- External Pullup
- TA_SOC_INTn
- Interrupt to SoC
- OUTPUT
- External Pullup
- 3.3V @ 200mA
sheet 21
- BOOT Mode Switch
- IO Expander
- BOOT Mode Buffer
- SWITCH ON  =  LOGIC 1
  SWITCH OFF =  LOGIC 0
- (From TA Header)
- (From TA Header)
- DIR = H: A -> B
  OE = H: output = Hi-Z
- AM243x LP - Boot-Mode selection table
- Boot Modes
  Supported
- Place these two TPs with 100mils
  spacing to insert external jumper
- SW4.1
- SW4.2
- SW4.3
- SW4.4
- SW4.5
- SW4.6
- SW4.7
- QSPI FLASH
- 0
- 1
- 0
- 0
- 0
- 1
- 0
- MMC1/SD Card
- 0
- 0
- 0
- 1
- 0
- 0
- 1
- UART
- 1
- 1
- 1
- 0
- 0
- 0
- 0
- USB - DFU
- 0
- 1
- 0
- 1
- 0
- 0
- 0
- No Boot
- 1
- 1
- 1
- 1
- 0
- 0
- 0
- BOOT_MODE0, 1 & 2 are used to select system Clock frequency
  (Default 25 MHz is selected)
- BOOT_MODE10, 11 & 12 are used to select Back-up Boot Mode
  (By Default No Back-up Boot mode is selected)
